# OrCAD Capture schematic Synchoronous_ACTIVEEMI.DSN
size Custom
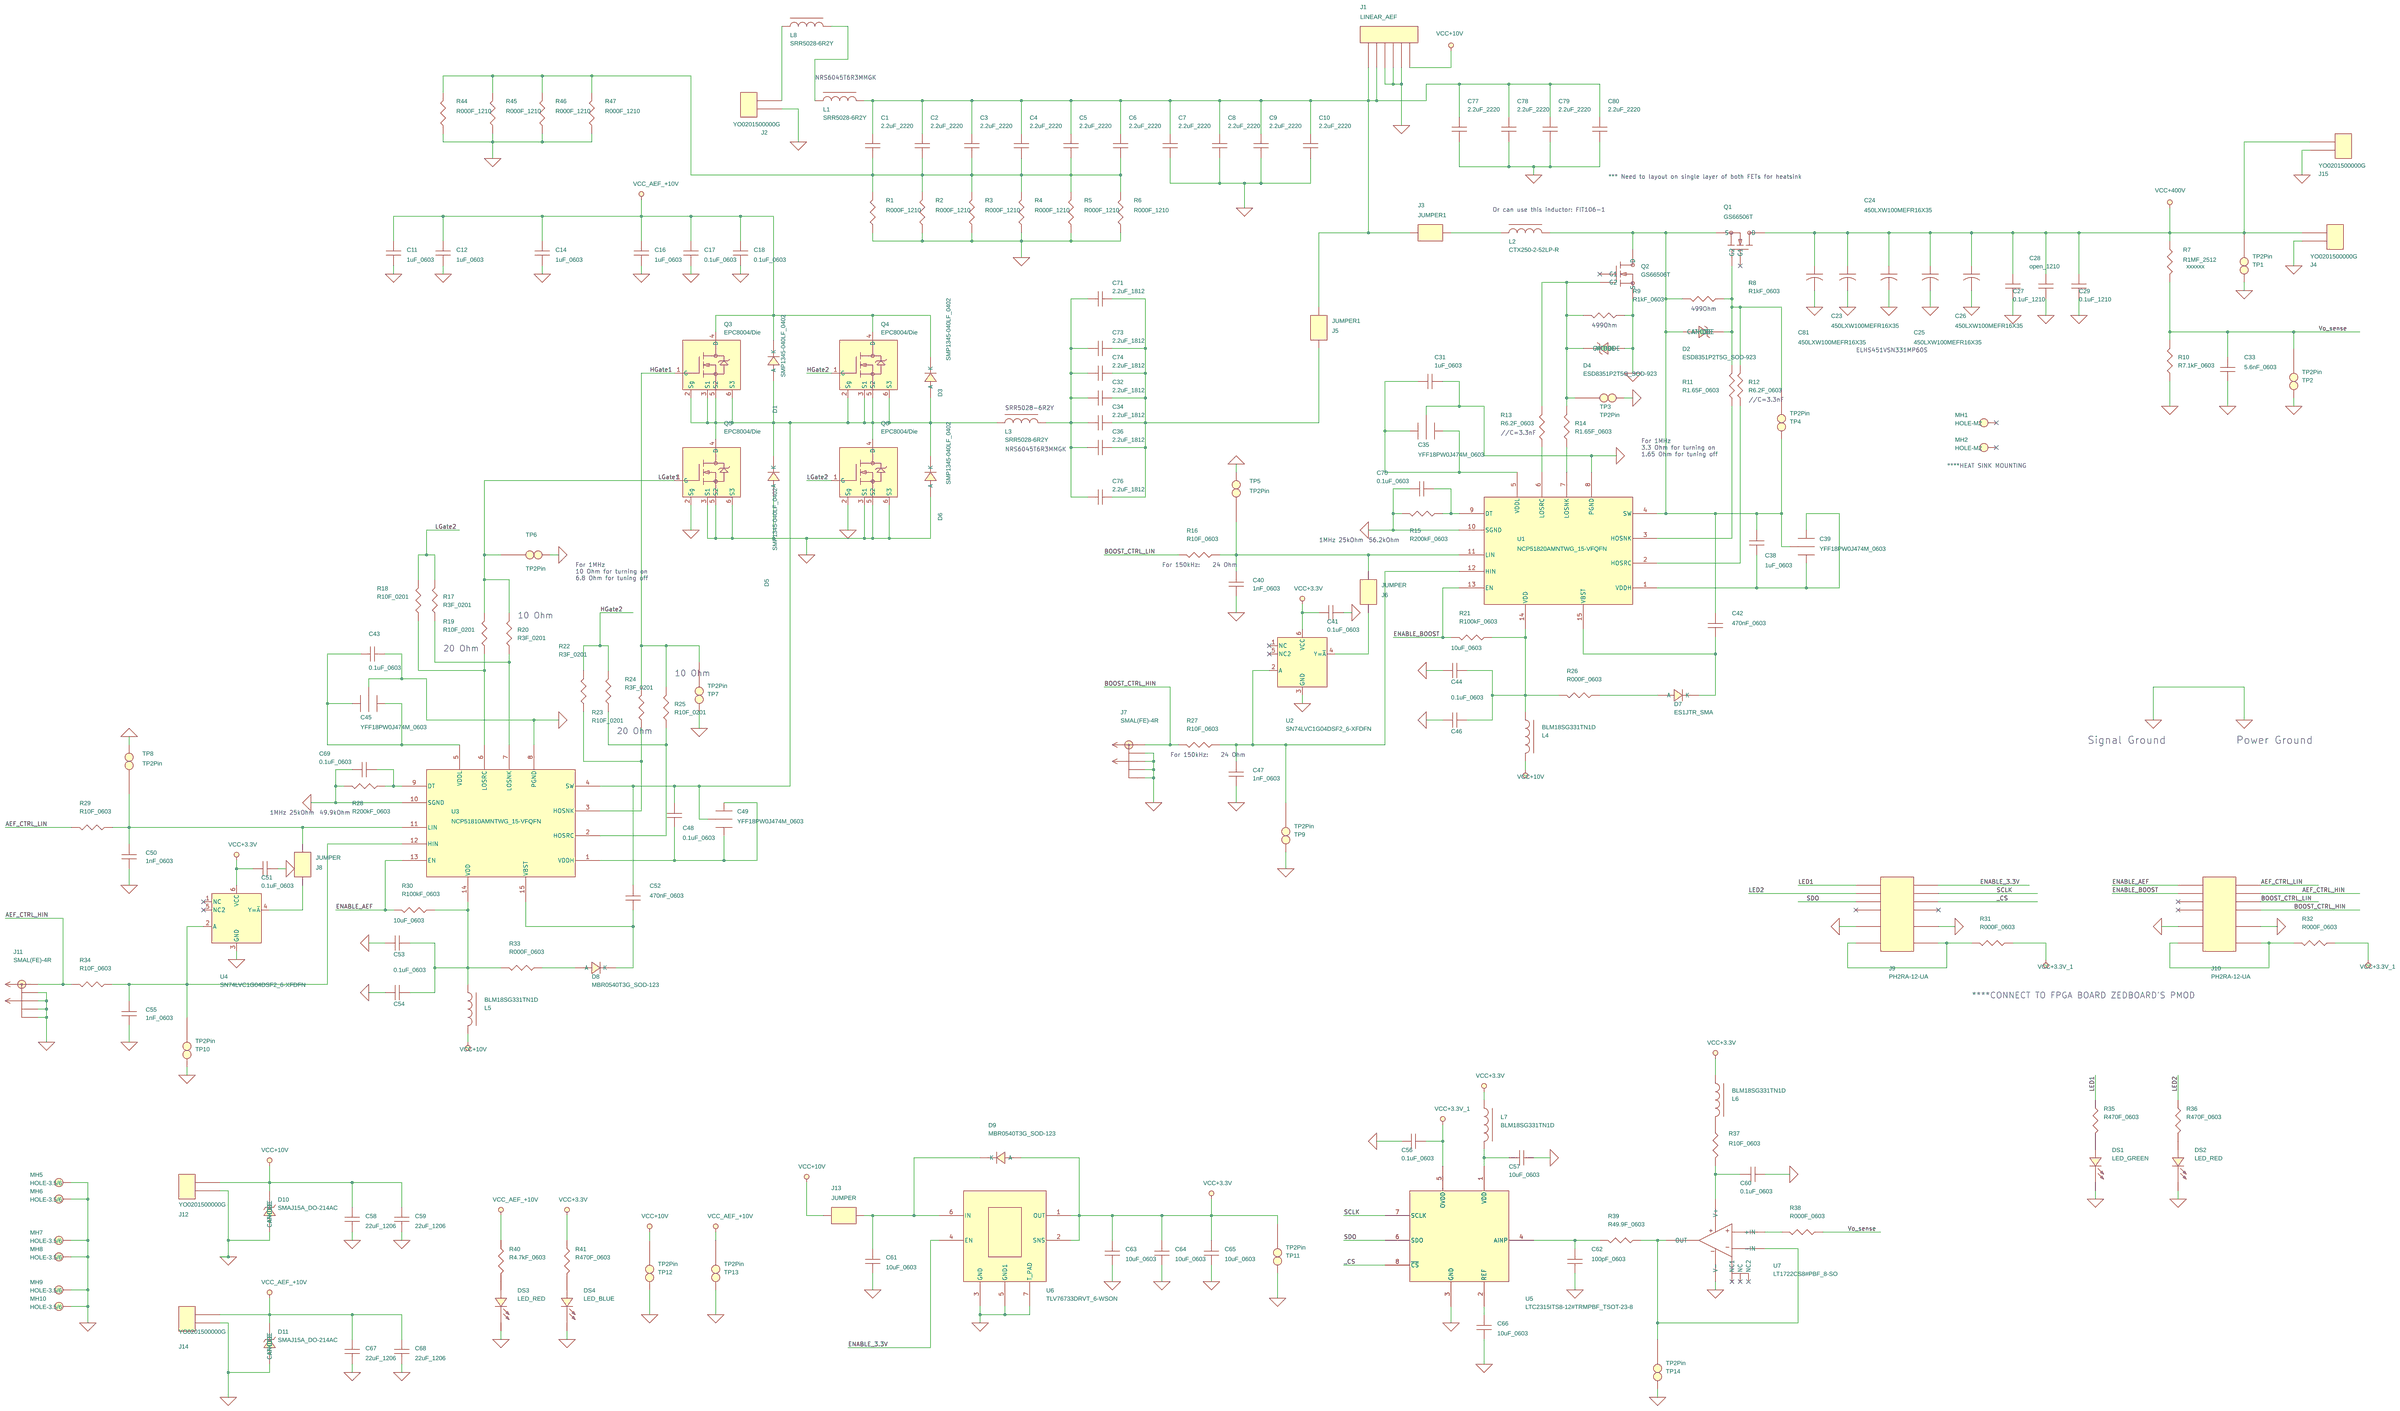
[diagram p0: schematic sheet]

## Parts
C1  2.2uF_2220  [ROC_CAP_021]
C2  2.2uF_2220  [ROC_CAP_021]
C3  2.2uF_2220  [ROC_CAP_021]
C4  2.2uF_2220  [ROC_CAP_021]
C5  2.2uF_2220  [ROC_CAP_021]
C6  2.2uF_2220  [ROC_CAP_021]
C7  2.2uF_2220  [ROC_CAP_021]
C8  2.2uF_2220  [ROC_CAP_021]
C9  2.2uF_2220  [ROC_CAP_021]
C10  2.2uF_2220  [ROC_CAP_021]
C11  1uF_0603  [C1608]
C12  1uF_0603  [C1608]
C14  1uF_0603  [C1608]
C16  1uF_0603  [C1608]
C17  0.1uF_0603  [C1608]
C18  0.1uF_0603  [C1608]
C23  450LXW100MEFR16X35  [450LXW100MEFR16X35]
C24  450LXW100MEFR16X35  [450LXW100MEFR16X35]
C25  450LXW100MEFR16X35  [450LXW100MEFR16X35]
C26  450LXW100MEFR16X35  [450LXW100MEFR16X35]
C27  0.1uF_1210  [22UF_1210]
C28  open_1210  [22UF_1210]
C29  0.1uF_1210  [22UF_1210]
C31  1uF_0603  [C1608]
C32  2.2uF_1812  [DJN_CAPACITOR_1812_MODIFIED_2.8MM]
C33  5.6nF_0603  [C1608]
C34  2.2uF_1812  [DJN_CAPACITOR_1812_MODIFIED_2.8MM]
C35  YFF18PW0J474M_0603  [FEEDTHRU_0603]
C36  2.2uF_1812  [DJN_CAPACITOR_1812_MODIFIED_2.8MM]
C38  1uF_0603  [C1608]
C39  YFF18PW0J474M_0603  [FEEDTHRU_0603]
C40  1nF_0603  [C1608]
C41  0.1uF_0603  [C1608]
C42  470nF_0603  [C1608]
C43  0.1uF_0603  [C1608]
C44  10uF_0603  [C1608]
C45  YFF18PW0J474M_0603  [FEEDTHRU_0603]
C46  0.1uF_0603  [C1608]
C47  1nF_0603  [C1608]
C48  0.1uF_0603  [C1608]
C49  YFF18PW0J474M_0603  [FEEDTHRU_0603]
C50  1nF_0603  [C1608]
C51  0.1uF_0603  [C1608]
C52  470nF_0603  [C1608]
C53  10uF_0603  [C1608]
C54  0.1uF_0603  [C1608]
C55  1nF_0603  [C1608]
C56  0.1uF_0603  [C1608]
C57  10uF_0603  [C1608]
C58  22uF_1206  [OPEN_1206]
C59  22uF_1206  [OPEN_1206]
C60  0.1uF_0603  [C1608]
C61  10uF_0603  [C1608]
C62  100pF_0603  [C1608]
C63  10uF_0603  [C1608]
C64  10uF_0603  [C1608]
C65  10uF_0603  [C1608]
C66  10uF_0603  [C1608]
C67  22uF_1206  [OPEN_1206]
C68  22uF_1206  [OPEN_1206]
C69  0.1uF_0603  [C1608]
C70  0.1uF_0603  [C1608]
C71  2.2uF_1812  [DJN_CAPACITOR_1812_MODIFIED_2.8MM]
C73  2.2uF_1812  [DJN_CAPACITOR_1812_MODIFIED_2.8MM]
C74  2.2uF_1812  [DJN_CAPACITOR_1812_MODIFIED_2.8MM]
C76  2.2uF_1812  [DJN_CAPACITOR_1812_MODIFIED_2.8MM]
C77  2.2uF_2220  [ROC_CAP_021]
C78  2.2uF_2220  [ROC_CAP_021]
C79  2.2uF_2220  [ROC_CAP_021]
C80  2.2uF_2220  [ROC_CAP_021]
C81  450LXW100MEFR16X35  [450LXW100MEFR16X35]
D1  SMP1345-040LF_0402  [SMP1345-040LF]
D2  ESD8351P2T5G_SOD-923  [ESD8351P2T5G]
D3  SMP1345-040LF_0402  [SMP1345-040LF]
D4  ESD8351P2T5G_SOD-923  [ESD8351P2T5G]
D5  SMP1345-040LF_0402  [SMP1345-040LF]
D6  SMP1345-040LF_0402  [SMP1345-040LF]
D7  ES1JTR_SMA  [SMAJ6.0CA_DO-214AC]
D8  MBR0540T3G_SOD-123  [MBR0540T3G_SOD-123]
D9  MBR0540T3G_SOD-123  [MBR0540T3G_SOD-123]
D10  SMAJ15A_DO-214AC  [SMAJ6.0CA_DO-214AC]
D11  SMAJ15A_DO-214AC  [SMAJ6.0CA_DO-214AC]
DS1  LED_GREEN  [598-8170-107F]
DS2  LED_RED  [598-8170-107F]
DS3  LED_RED  [598-8170-107F]
DS4  LED_BLUE  [598-8170-107F]
J1  LINEAR_AEF  [LINEAR_AEF_CONN]
J2  YO0201500000G  [YO0201500000G]
J3  JUMPER1  [JUMPER3]
J4  YO0201500000G  [YO0201500000G]
J5  JUMPER1  [JUMPER3]
J6  JUMPER  [JUMPER]
J7  SMAL(FE)-4R  [SMBL(FE)-4R]
J8  JUMPER  [JUMPER]
J9  PH2RA-12-UA  [PH2RA-12-UA]
J10  PH2RA-12-UA  [PH2RA-12-UA]
J11  SMAL(FE)-4R  [SMBL(FE)-4R]
J12  YO0201500000G  [YO0201500000G]
J13  JUMPER  [JUMPER]
J14  YO0201500000G  [YO0201500000G]
J15  YO0201500000G  [YO0201500000G]
L1  SRR5028-6R2Y  [SRR5028-6R2Y]
L2  CTX250-2-52LP-R  [CTX250-2-52LP-R]
L3  SRR5028-6R2Y  [SRR5028-6R2Y]
L4  BLM18SG331TN1D  [L1608]
L5  BLM18SG331TN1D  [L1608]
L6  BLM18SG331TN1D  [L1608]
L7  BLM18SG331TN1D  [L1608]
L8  SRR5028-6R2Y  [SRR5028-6R2Y]
MH1  HOLE-M2  [HOLE-2.2/3.6]
MH2  HOLE-M2  [HOLE-2.2/3.6]
MH5  HOLE-3.5/6  [HOLE-3.2/6]
MH6  HOLE-3.5/6  [HOLE-3.2/6]
MH7  HOLE-3.5/6  [HOLE-3.2/6]
MH8  HOLE-3.5/6  [HOLE-3.2/6]
MH9  HOLE-3.5/6  [HOLE-3.2/6]
MH10  HOLE-3.5/6  [HOLE-3.2/6]
Q1  GS66506T  [GS66506T]
Q2  GS66506T  [GS66506T]
Q3  EPC8004/Die  [EPC8004/DIE]
Q4  EPC8004/Die  [EPC8004/DIE]
Q5  EPC8004/Die  [EPC8004/DIE]
Q6  EPC8004/Die  [EPC8004/DIE]
R1  R000F_1210  [1R0_1210]
R2  R000F_1210  [1R0_1210]
R3  R000F_1210  [1R0_1210]
R4  R000F_1210  [1R0_1210]
R5  R000F_1210  [1R0_1210]
R6  R000F_1210  [1R0_1210]
R7  R1MF_2512  [R_2512]
R8  R1kF_0603  [R_1608]
R9  R1kF_0603  [R_1608]
R10  R7.1kF_0603  [R_1608]
R11  R1.65F_0603  [R_1608]
R12  R6.2F_0603  [R_1608]
R13  R6.2F_0603  [R_1608]
R14  R1.65F_0603  [R_1608]
R15  R200kF_0603  [R_1608]
R16  R10F_0603  [R_1608]
R17  R3F_0201  [R_0201]
R18  R10F_0201  [R_0201]
R19  R10F_0201  [R_0201]
R20  R3F_0201  [R_0201]
R21  R100kF_0603  [R_1608]
R22  R3F_0201  [R_0201]
R23  R10F_0201  [R_0201]
R24  R3F_0201  [R_0201]
R25  R10F_0201  [R_0201]
R26  R000F_0603  [R_1608]
R27  R10F_0603  [R_1608]
R28  R200kF_0603  [R_1608]
R29  R10F_0603  [R_1608]
R30  R100kF_0603  [R_1608]
R31  R000F_0603  [R_1608]
R32  R000F_0603  [R_1608]
R33  R000F_0603  [R_1608]
R34  R10F_0603  [R_1608]
R35  R470F_0603  [R_1608]
R36  R470F_0603  [R_1608]
R37  R10F_0603  [R_1608]
R38  R000F_0603  [R_1608]
R39  R49.9F_0603  [R_1608]
R40  R4.7kF_0603  [R_1608]
R41  R470F_0603  [R_1608]
R44  R000F_1210  [1R0_1210]
R45  R000F_1210  [1R0_1210]
R46  R000F_1210  [1R0_1210]
R47  R000F_1210  [1R0_1210]
TP1  TP2Pin  [TP2PIN]
TP2  TP2Pin  [TP2PIN]
TP3  TP2Pin  [TP2PIN]
TP4  TP2Pin  [TP2PIN]
TP5  TP2Pin  [TP2PIN]
TP6  TP2Pin  [TP2PIN]
TP7  TP2Pin  [TP2PIN]
TP8  TP2Pin  [TP2PIN]
TP9  TP2Pin  [TP2PIN]
TP10  TP2Pin  [TP2PIN]
TP11  TP2Pin  [TP2PIN]
TP12  TP2Pin  [TP2PIN]
TP13  TP2Pin  [TP2PIN]
TP14  TP2Pin  [TP2PIN]
U1  NCP51820AMNTWG_15-VFQFN  [NCP51810AMNTWG]
U2  SN74LVC1G04DSF2_6-XFDFN  [SN74LVC1G04DSF2]
U3  NCP51810AMNTWG_15-VFQFN  [NCP51810AMNTWG]
U4  SN74LVC1G04DSF2_6-XFDFN  [SN74LVC1G04DSF2]
U5  LTC2315ITS8-12#TRMPBF_TSOT-23-8  [LTC2315ITS8-12_TSOT-23-8]
U6  TLV76733DRVT_6-WSON  [TLV76733DRVT_6-WSON]
U7  LT1722CS8#PBF_8-SO  [DJN_IC_8-SOIC]

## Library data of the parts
C1-C10 C27-C29 C31-C34 C36 C38 C40-C44 C46-C48 C50-C57 C60-C66 C69-C71 C73 C74 C76-C80 = CAP_NP_1
C11 C12 C14 C16-C18 C58 C59 C67 C68 = CAP_NP_1: PART NO: 151273
C23-C26 C81 = CAP_0
C35 C39 C45 C49 = CAP_NP_0
D1 D3 D5 D6 = DIODE_1
D2 D4 = DIODE_ZENER_0: PART NO: 40002129
D7-D9 = DIODE_5: PART NO: 40001919
D10 D11 = DIODE_ZENER_0
DS1-DS4 = LED_0
J1 = CON6
J2 J4 J12 J14 J15 = CON2
J3 J5 J6 J8 J13 = CON2_1
J7 J11 = 142-0701-506_0
J9 J10 = CON12A_0
L1-L3 L8 = INDUCTOR_4
L4-L7 = CHOKE_1
MH1 MH2 MH5-MH10 = T_POINT_R
Q1 Q2 = IRFZ24N_TO_5: PART NO: 1063683; PATH NO: 1063683
Q3-Q6 = IRFZ24N_TO_2: PATH NO: 1063683
R1-R6 R8-R34 R37-R39 R44-R47 = R_0
R7 = RESISTOR_0: PART NO: xxxxxx
R35 R36 R40 R41 = RESISTOR
TP1-TP14 = T_POINT_R_1
U1 U3 = CON8A_4
U2 U4 = CON6A_0
U5 = CON8A_7
U6 = CON8A_6
U7 = OPA658_SOT_3

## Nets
GND_POWER: C7.2 C8.2 C9.2 C10.2 C11.2 C12.2 C14.2 C16.2 C17.2 C18.2 C23.2 C24.2 C25.2 C26.2 C27.2 C28.2 C29.2 C31.2 C33.1 C35.3 C40.1 C41.2 C43.2 C44.1 C45.3 C46.1 C47.1 C50.1 C51.2 C53.1 C54.1 C55.1 C56.1 C57.1 C58.2 C59.2 C60.1 C61.1 C62.1 C63.1 C64.1 C65.1 C66.1 C67.2 C68.2 C69.1 C70.1 C77.2 C78.2 C79.2 C80.2 C81.2 D4.1(ANODE) D5.1(A) D6.1(A) D10.1(ANODE) D11.1(ANODE) DS1.1(CATHODE) DS2.1(CATHODE) DS3.1(CATHODE) DS4.1(CATHODE) J1.3 J1.4 J1.5 J2.1 J4.1 J7.2 J7.3 J7.4 J7.5 J9.9 J9.10 J10.9 J10.10 J11.2 J11.3 J11.4 J11.5 J12.1 J14.1 J15.1 MH5.1(TP) MH6.1(TP) MH7.1(TP) MH8.1(TP) MH9.1(TP) MH10.1(TP) Q2.3(S) Q5.2(Sg) Q5.3(S1) Q5.5(S2) Q5.6(S3) Q6.2(Sg) Q6.3(S1) Q6.5(S2) Q6.6(S3) R1.2 R2.2 R3.2 R4.2 R5.2 R6.2 R9.2 R10.2 R15.1 R28.1 R44.2 R45.2 R46.2 R47.2 TP1.2(GND) TP2.2(GND) TP3.2(GND) TP5.2(GND) TP6.2(GND) TP7.2(GND) TP8.2(GND) TP9.2(GND) TP10.2(GND) TP11.2(GND) TP12.2(GND) TP13.2(GND) TP14.2(GND) U1.8(PGND) U1.10(SGND) U2.3(GND) U3.8(PGND) U3.10(SGND) U4.3(GND) U5.3(GND) U6.3(GND) U6.5(GND1) U6.7(T_PAD) U7.4(V-)
Vcc+3.3V: C41.1 C51.1 C63.2 C64.2 C65.2 D9.1(A) L6.2 L7.2 R41.1 TP11.1(TP) U2.6(VCC) U4.6(VCC) U6.1(OUT) U6.2(SNS)
Vcc+3.3V_1: C56.2 R31.2 R32.2 U5.5(OVDD)
Vcc+10V: C58.1 C59.1 D10.2(CATHODE) J1.6 J12.2 J13.1 L4.1 L5.1 TP12.1(TP)
Vcc+400V: C23.1 C24.1 C25.1 C26.1 C27.1 C28.1 C29.1 C81.1 J4.2 J15.2 Q1.1(D) R7.1 TP1.1(TP)
Vcc_AEF_+10V: C11.1 C12.1 C14.1 C16.1 C17.1 C18.1 C67.1 C68.1 D1.2(K) D3.2(K) D11.2(CATHODE) J14.2 Q3.4(D) Q4.4(D) R40.1 TP13.1(TP)
_CS: J9.6 U5.8(~{CS})
AEF_CTRL_HIN: J10.4 J11.1 R34.1
AEF_CTRL_LIN: J10.2 R29.1
BOOST_CTRL_HIN: J7.1 J10.8 R27.1
BOOST_CTRL_LIN: J10.6 R16.1
ENABLE_3.3V: J9.2 U6.4(EN)
ENABLE_AEF: J10.1 R30.1 U3.13(EN)
ENABLE_BOOST: J10.3 R21.1 U1.13(EN)
HGate1: Q3.1(G) R24.1 R25.1 TP7.1(TP)
HGate2: Q4.1(G) R22.1 R23.1
LED1: J9.1 R35.1
LED2: J9.3 R36.1
LGate1: Q5.1(G) R19.1 R20.1 TP6.1(TP)
LGate2: Q6.1(G) R17.1 R18.1
SCLK: J9.4 U5.7(SCLK)
SDO: J9.5 U5.6(SDO)
Vo_sense: C33.2 R7.2 R10.1 R38.2 TP2.1(TP)
N14603984: C44.2 C46.2 L4.2 R21.2 R26.1 U1.14(VDD)
N14608593: C38.2 C39.3 C42.2 D2.1(ANODE) L2.2 Q1.3(S) Q2.1(D) R8.1 TP4.2(GND) U1.4(SW)
N14621888: C40.2 J6.1 R16.2 TP5.1(TP) U1.11(LIN)
N14733539: D2.2(CATHODE) Q1.4(G2) R8.2 R11.1 R12.1 TP4.1(TP)
N14733579: R11.2 U1.3(HOSNK)
N14733586: R12.2 U1.2(HOSRC)
N14733638: C38.1 C39.1 C39.2 U1.1(VDDH)
N14737096: D4.2(CATHODE) Q2.4(G2) R9.1 R13.1 R14.1 TP3.1(TP)
N14737145: R14.2 U1.7(LOSNK)
N14737193: R13.2 U1.6(LOSRC)
N14740178: C31.1 C35.1 C35.2 U1.5(VDDL)
N14741139: C42.1 D7.2(K) U1.15(VBST)
N14748206: C70.2 R15.2 U1.9(DT)
N14756321: C47.2 R27.2 TP9.1(TP) U1.12(HIN) U2.2(A)
N14763076: D7.1(A) R26.2
N14791886: C43.1 C45.1 C45.2 U3.5(VDDL)
N14791966: R22.2 R24.2 U3.3(HOSNK)
N14791970: R23.2 R25.2 U3.2(HOSRC)
N14792026: R18.2 R19.2 U3.6(LOSRC)
N14792030: R17.2 R20.2 U3.7(LOSNK)
N14792154: C69.2 R28.2 U3.9(DT)
N14792158: C48.2 C49.3 C52.2 D1.1(A) D3.1(A) D5.2(K) D6.2(K) L3.1 Q3.2(Sg) Q3.3(S1) Q3.5(S2) Q3.6(S3) Q4.2(Sg) Q4.3(S1) Q4.5(S2) Q4.6(S3) Q5.4(D) Q6.4(D) U3.4(SW)
N14792190: C48.1 C49.1 C49.2 U3.1(VDDH)
N14792198: C50.2 J8.1 R29.2 TP8.1(TP) U3.11(LIN)
N14792348: C55.2 R34.2 TP10.1(TP) U3.12(HIN) U4.2(A)
N14792458: C53.2 C54.2 L5.2 R30.2 R33.1 U3.14(VDD)
N14792462: C52.1 D8.2(K) U3.15(VBST)
N14792694: D8.1(A) R33.2
N14800643: C32.2 C34.2 C36.2 C71.2 C73.2 C74.2 C76.2 L3.2
N14800647: C32.1 C34.1 C36.1 C71.1 C73.1 C74.1 C76.1 J5.2
N14802479: J3.2 L2.1
N14802530: C1.1 C2.1 C3.1 C4.1 C5.1 C6.1 C7.1 C8.1 C9.1 C10.1 C77.1 C78.1 C79.1 C80.1 J1.1 J1.2 J3.1 J5.1 L1.2
N14827934: C62.2 R39.1 U5.4(AINP)
N14828712: R39.2 TP14.1(TP) U7.2(-IN) U7.6(OUT)
N14829182: R38.1 U7.3(+IN)
N14829837: C57.2 L7.1 U5.1(VDD)
N14832157: C60.2 R37.1 U7.7(V+)
N14837897: J8.2 U4.4(Y=~{A})
N14839327: J6.2 U2.4(Y=~{A})
N14852069: C61.2 D9.2(K) J13.2 U6.6(IN)
N14856029: J9.11 J9.12 R31.1
N14891719: C66.2 U5.2(REF)
N14898438: J10.11 J10.12 R32.1
N14915199: C1.2 C2.2 C3.2 C4.2 C5.2 C6.2 R1.1 R2.1 R3.1 R4.1 R5.1 R6.1 R44.1 R45.1 R46.1 R47.1
N14931483: DS1.2(ANODE) R35.2
N14931484: L6.1 R37.2
N14931485: DS2.2(ANODE) R36.2
N14931486: DS4.2(ANODE) R41.2
N14931487: DS3.2(ANODE) R40.2
N14958440: J2.2 L8.1
N14958444: L1.1 L8.2

Not connected (* = marked no-connect by the designer): J9 7* 8*; J10 5* 7*; MH1 1(TP)*; MH2 1(TP)*; Q1 2(G1)*; Q2 2(G1)*; U2 1(NC)* 5(NC2)*; U4 1(NC)* 5(NC2)*; U7 1(NC2)* 5(NC)* 8(NC1)*

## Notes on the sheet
- NRS6045T6R3MMGK
- *** Need to layout on single layer of both FETs for heatsink
- Or can use this inductor: FIT106-1
- 499Ohm
- 499Ohm
- ELHS451VSN331MP60S
- //C=3.3nF
- SRR5028-6R2Y
- //C=3.3nF
- For 1MHz
  3.3 Ohm for turning on
  1.65 Ohm for tuning off
- NRS6045T6R3MMGK
- ****HEAT SINK MOUNTING
- 1MHz 25kOhm
- 56.2kOhm
- For 1MHz
  10 Ohm for turning on
  6.8 Ohm for tuning off
- For 150kHz:    24 Ohm
- 10 Ohm
- 20 Ohm
- 10 Ohm
- 20 Ohm
- Signal Ground
- Power Ground
- For 150kHz:    24 Ohm
- 1MHz 25kOhm
- 49.9kOhm
- ****CONNECT TO FPGA BOARD ZEDBOARD'S PMOD
